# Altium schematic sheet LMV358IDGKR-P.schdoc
size 127 x 101 mm
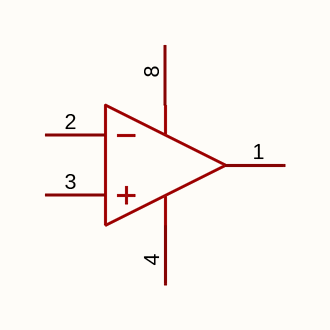
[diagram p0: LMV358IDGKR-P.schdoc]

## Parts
U?  lmv358idgkr-p  [MSOP-8_L3.0-W3.0-P0.65-LS4.9-BL]  (value not drawn)  (part A of 2)

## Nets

Not connected (* = marked no-connect by the designer): U? 1(OUTA) 2(INA-) 3(INA+) 4(VSS) 8(VDD)

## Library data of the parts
U? = lmv358idgkr-p: 放大器数:2;轨到轨:轨到轨输入,轨到轨输出;增益带宽积(GBW):1MHz;输入失调电压(Vos):5mV;压摆率(SR):600V/ms;输入偏置电流(Ib):10pA;; Manufacturer: TECH PUBLIC(台舟); AddInBom: yes; ModelId: bedc0aeebe0a475e87aaac88bd02a14b; ModelName: MSOP-8_L3.0-W3.0-H1.1-LS4.9-P0.65; ModelTransform: 118.11,192.913,0,0,0,0,0,0,0; Number of Channels: 2; Maximum Power Supply Range (Vdd-Vss): 5.5V; Gain Bandwidth Product: 1MHz; Vos - Input Offset Voltage: 5mV; Input Offset Voltage Drift(Vos TC): 2uV/℃; Ib - Input Bias Current: 10pA; Input Voltage Noise Density: 20nV/√Hz@10kHz; Common Mode Rejection Ratio(CMRR): 65dB; Quiescent Current: 40uA; Output Current: 20mA; Single supply: 2.5V~5.5V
